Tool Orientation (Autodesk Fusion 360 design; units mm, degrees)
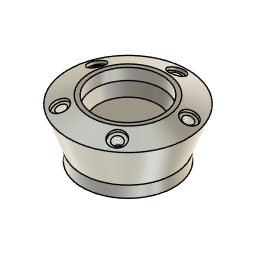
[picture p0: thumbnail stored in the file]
sketch "Sketch1" plane through (0, 0, 0) normal (1, 0, 0) x axis (0, 1, 0)
  line L1 (0, 63.5) -> (0, 0)
  line L2 (42.2596, 63.5) -> (0, 63.5)
  line L3 (66.1278, 54.8127) -> (42.2596, 63.5)
  line L4 (50.8, 12.7) -> (66.1278, 54.8127)
  line L5 (50.8, 0) -> (50.8, 12.7)
  line L6 (0, 0) -> (50.8, 0)
  line L7 (37.6371, 50.8) -> (37.6371, 63.5)
  line L8 (33.0147, 38.1) -> (37.6371, 50.8)
  line L9 (0, 38.1) -> (33.0147, 38.1)
  line L10 (42.2596, 63.5) -> (37.6371, 50.8)
  point P1 (0, 0)
  point P2 (0, 0)
  point P8 (0, 0)
  point P9 (37.6371, 63.5)
  point P12 (0, 38.1)
  point P6 (50.8, 12.7)
  point P7 (50.8, 0)
  point P4 (42.2596, 63.5)
  point P5 (66.1278, 54.8127)
  point P3 (0, 63.5)
  point P10 (37.6371, 50.8)
  coincident P1 P2
  vertical L1
  perpendicular L1 L2
  perpendicular L2 L5
  coincident P1 P8
  horizontal L6
  perpendicular L3 L4
  coincident L2 P9
  perpendicular L2 L7
  coincident L1 P12
  perpendicular L1 L9
  collinear L8 L10
  parallel L4 L10
  dimension "d1" = 101.6
  dimension "d2" distance P6 P7 = 12.7
  dimension "d3" angle L4 L5 = 20
  dimension "d4" distance P4 P5 = 25.4
  dimension "d5" distance P2 P3 = 63.5
  dimension "d7" distance P9 P10 = 12.7
  dimension "d8" distance L2 L9 = 25.4
revolve "Revolve1" sketch "Sketch1" AlongAngle 360 bodies "Part"
work_plane "WorkPlane1" RotateAngle 0
sketch "Sketch2" plane through (0, 54.1937, 59.1563) normal (0, 0.342, 0.9397) x axis (0, 0.9397, -0.342)
  circle C1 centre (0, 0) radius 8.903
  point P1 (0, 0)
  point P2 (0, 0)
  coincident P1 P2
  dimension "d10" diameter C1 = 17.806
copy_paste_bodies "CopyPasteBodies1"
extrude "Extrude1" cut sketch "Sketch2" against normal blind 3.175
hole "Hole1" HoleDepth 12.7 HoleDiameter 10.6426 TipAngle 118
circular_pattern "C-Pattern1" TotalAngle 360
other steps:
base_feature "Base Feature" bodies "Stock"
thread "Thread1" ThreadOffset 0 ThreadDepth 10.0076
named bodies: "Part", "Stock"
